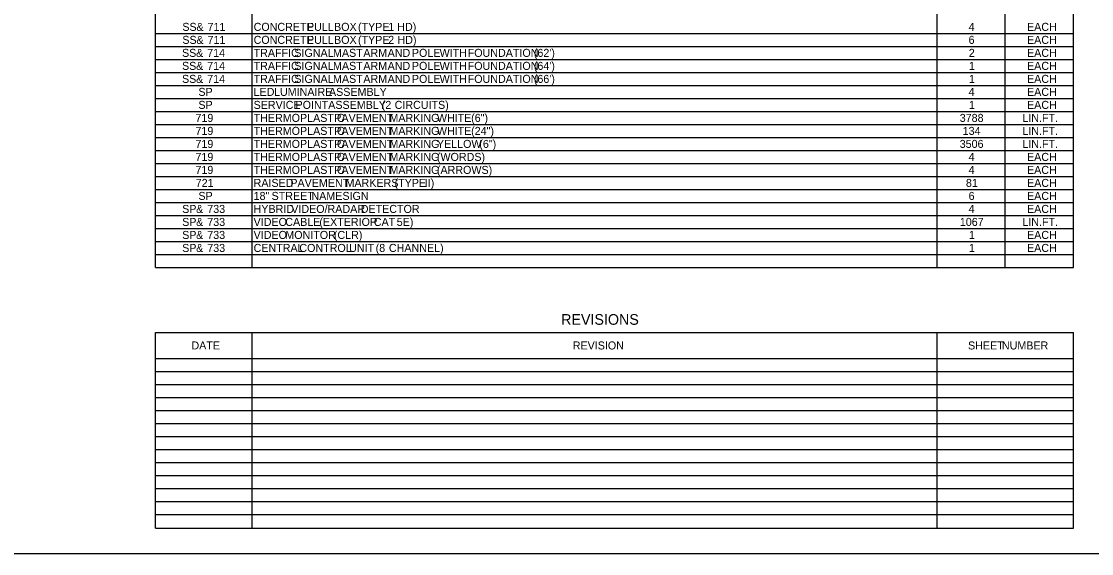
# Model space of a CAD drawing. Extents: x 3289 to 10164, y -1238 to -188.
# Drawn here: x 8800 to 9602, y -1238 to -839 of the extents above; entities that cross this region are included whole.
import ezdxf

# ---------------------------------------------------------------- set-up
doc = ezdxf.new("R2010")
doc.units = 0
for name, color, linetype in [('Default', 7, 'Continuous'), ('DSN_DRFT_Named-Boundary', 7, 'Continuous'), ('DSN_QNTY_Annotation', 7, 'Continuous')]:
    doc.layers.add(name, color=color, linetype=linetype)

msp = doc.modelspace()

# ---------------------------------------------------------------- linework, layer by layer
at = {"layer": 'DSN_DRFT_Named-Boundary'}
msp.add_lwpolyline([(8538.57, -1237.74), (10163.57, -1237.74), (10163.57, -187.74), (8538.57, -187.74)], close=True, dxfattribs=at)
at = {"layer": 'DSN_QNTY_Annotation'}
for p, q in [((8900.84, -1023.18), (8900.84, -223.68)), ((8973.38, -1023.18), (8973.38, -223.68)), ((9486.62, -1023.18), (9486.62, -223.68)), ((9537.71, -1023.18), (9537.71, -223.68)), ((9537.71, -1023.18), (9537.71, -223.68)), ((9588.8, -1023.18), (9588.8, -223.68)), ((8973.38, -1023.18), (8973.38, -252.93)), ((8900.84, -847.68), (9588.8, -847.68)), ((9486.62, -1023.18), (9486.62, -847.68)), ((8900.84, -857.43), (9588.8, -857.43)), ((9396.53, -857.43), (9486.62, -857.43)), ((9486.62, -857.43), (9588.8, -857.43)), ((8900.84, -867.18), (9588.8, -867.18)), ((8900.84, -876.93), (9588.8, -876.93)), ((8900.84, -886.68), (9588.8, -886.68)), ((8900.84, -896.43), (9588.8, -896.43)), ((8900.84, -906.18), (9588.8, -906.18)), ((8900.84, -915.93), (9588.8, -915.93)), ((8900.84, -925.68), (9588.8, -925.68)), ((8900.84, -935.43), (9588.8, -935.43)), ((8900.84, -945.18), (9588.8, -945.18)), ((8900.84, -954.93), (9588.8, -954.93)), ((8900.84, -964.68), (9588.8, -964.68)), ((8900.84, -974.43), (9588.8, -974.43)), ((8900.84, -984.18), (9588.8, -984.18)), ((8900.84, -993.93), (9588.8, -993.93)), ((8900.84, -1003.68), (9588.8, -1003.68)), ((8900.84, -1013.43), (9588.8, -1013.43)), ((8900.84, -1023.18), (9588.8, -1023.18)), ((8900.84, -1071.93), (9588.8, -1071.93)), ((8900.84, -1071.93), (8973.38, -1071.93)), ((8900.84, -1218.57), (8900.84, -1071.93)), ((8973.38, -1218.57), (8973.38, -1071.93)), ((9486.62, -1071.93), (9588.8, -1071.93)), ((9486.62, -1091.43), (9486.62, -1071.93)), ((9486.62, -1218.57), (9486.62, -1071.93)), ((9588.8, -1218.57), (9588.8, -1071.93)), ((8900.84, -1091.43), (9588.8, -1091.43)), ((8900.84, -1101.18), (9588.8, -1101.18)), ((8900.84, -1110.93), (9588.8, -1110.93)), ((8900.84, -1120.68), (9588.8, -1120.68)), ((8900.84, -1130.43), (9588.8, -1130.43)), ((8900.84, -1140.18), (9588.8, -1140.18)), ((8900.84, -1149.93), (9588.8, -1149.93)), ((8900.84, -1159.68), (9588.8, -1159.68)), ((8900.84, -1169.43), (9588.8, -1169.43)), ((8900.84, -1179.18), (9588.8, -1179.18)), ((8900.84, -1188.93), (9588.8, -1188.93)), ((8900.84, -1198.68), (9588.8, -1198.68)), ((8900.84, -1208.43), (9588.8, -1208.43)), ((8900.84, -1218.57), (9588.8, -1218.57))]:
    msp.add_line(p, q, dxfattribs=at)

# ---------------------------------------------------------------- texts
at = {"layer": 'Default'}
for s, height, p in [('SS', 6, (8920.95, -845.81)), (' &', 6, (8929.26, -845.81)), (' 711', 6, (8937.6, -845.81)), ('CONCRETE', 6, (8974.36, -845.81)), (' PULL', 6, (9012.13, -845.81)), (' BOX', 6, (9032.42, -845.81)), (' (TYPE', 6, (9050.36, -845.81)), (' 1', 6, (9073.01, -845.81)), (' HD)', 6, (9079.8, -845.81)), ('4', 6, (9510.23, -845.81)), ('EACH', 6, (9554.03, -845.81)), ('SS', 6, (8920.95, -855.56)), (' &', 6, (8929.26, -855.56)), (' 711', 6, (8937.6, -855.56)), ('CONCRETE', 6, (8974.36, -855.56)), (' PULL', 6, (9012.13, -855.56)), (' BOX', 6, (9032.42, -855.56)), (' (TYPE', 6, (9050.36, -855.56)), (' 2', 6, (9073.01, -855.56)), (' HD)', 6, (9079.98, -855.56)), ('6', 6, (9510.25, -855.56)), ('EACH', 6, (9554.03, -855.56)), ('SS', 6, (8920.71, -865.31)), (' &', 6, (8929.01, -865.31)), (' 714', 6, (8937.36, -865.31)), ('TRAFFIC', 6, (8974.36, -865.31)), (' SIGNAL', 6, (9002.66, -865.31)), (' MAST', 6, (9031.64, -865.31)), (' ARM', 6, (9054.38, -865.31)), (' AND', 6, (9072.58, -865.31)), (' POLE', 6, (9090.77, -865.31)), (' WITH', 6, (9111.56, -865.31)), (' FOUNDATION', 6, (9132.58, -865.31)), (" (62')", 6, (9182.15, -865.31)), ('2', 6, (9510.38, -865.31)), ('EACH', 6, (9554.03, -865.31)), ('SS', 6, (8920.71, -875.06)), (' &', 6, (8929.01, -875.06)), (' 714', 6, (8937.36, -875.06)), ('TRAFFIC', 6, (8974.36, -875.06)), (' SIGNAL', 6, (9002.66, -875.06)), (' MAST', 6, (9031.64, -875.06)), (' ARM', 6, (9054.38, -875.06)), (' AND', 6, (9072.58, -875.06)), (' POLE', 6, (9090.77, -875.06)), (' WITH', 6, (9111.56, -875.06)), (' FOUNDATION', 6, (9132.58, -875.06)), (" (64')", 6, (9182.15, -875.06)), ('1', 6, (9510.47, -875.06)), ('EACH', 6, (9554.03, -875.06)), ('SS', 6, (8920.71, -884.81)), (' &', 6, (8929.01, -884.81)), (' 714', 6, (8937.36, -884.81)), ('TRAFFIC', 6, (8974.36, -884.81)), (' SIGNAL', 6, (9002.66, -884.81)), (' MAST', 6, (9031.64, -884.81)), (' ARM', 6, (9054.38, -884.81)), (' AND', 6, (9072.58, -884.81)), (' POLE', 6, (9090.77, -884.81)), (' WITH', 6, (9111.56, -884.81)), (' FOUNDATION', 6, (9132.58, -884.81)), (" (66')", 6, (9182.15, -884.81)), ('1', 6, (9510.47, -884.81)), ('EACH', 6, (9554.03, -884.81)), ('SP', 6, (8932.99, -894.56)), ('LED', 6, (8974.36, -894.56)), (' LUMINAIRE', 6, (8987.45, -894.56)), (' ASSEMBLY', 6, (9028.63, -894.56)), ('4', 6, (9510.23, -894.56)), ('EACH', 6, (9554.03, -894.56)), ('SP', 6, (8932.99, -904.31)), ('SERVICE', 6, (8974.36, -904.31)), (' POINT', 6, (9003.55, -904.31)), (' ASSEMBLY', 6, (9028.05, -904.31)), (' (2', 6, (9068.16, -904.31)), (' CIRCUITS)', 6, (9077.85, -904.31)), ('1', 6, (9510.47, -904.31)), ('EACH', 6, (9554.03, -904.31)), ('719', 6, (8930.78, -914.06)), ('THERMOPLASTIC', 6, (8974.36, -914.06)), (' PAVEMENT', 6, (9032.6, -914.06)), (' MARKING', 6, (9073.94, -914.06)), (' WHITE', 6, (9109.51, -914.06)), (' (6")', 6, (9135.17, -914.06)), ('3788', 6, (9503.61, -914.06)), ('LIN.', 6, (9550.54, -914.06)), (' FT.', 6, (9563, -914.06)), ('719', 6, (8930.78, -923.81)), ('THERMOPLASTIC', 6, (8974.36, -923.81)), (' PAVEMENT', 6, (9032.6, -923.81)), (' MARKING', 6, (9073.94, -923.81)), (' WHITE', 6, (9109.51, -923.81)), (' (24")', 6, (9135.17, -923.81)), ('134', 6, (9505.79, -923.81)), ('LIN.', 6, (9550.54, -923.81)), (' FT.', 6, (9563, -923.81)), ('719', 6, (8930.78, -933.56)), ('THERMOPLASTIC', 6, (8974.36, -933.56)), (' PAVEMENT', 6, (9032.6, -933.56)), (' MARKING', 6, (9073.94, -933.56)), (' YELLOW', 6, (9109.51, -933.56)), (' (6")', 6, (9141.31, -933.56)), ('3506', 6, (9503.59, -933.56)), ('LIN.', 6, (9550.54, -933.56)), (' FT.', 6, (9563, -933.56)), ('719', 6, (8930.78, -943.31)), ('THERMOPLASTIC', 6, (8974.36, -943.31)), (' PAVEMENT', 6, (9032.6, -943.31)), (' MARKING', 6, (9073.94, -943.31)), (' (WORDS)', 6, (9109.51, -943.31)), ('4', 6, (9510.23, -943.31)), ('EACH', 6, (9554.03, -943.31)), ('719', 6, (8930.78, -953.06)), ('THERMOPLASTIC', 6, (8974.36, -953.06)), (' PAVEMENT', 6, (9032.6, -953.06)), (' MARKING', 6, (9073.94, -953.06)), (' (ARROWS)', 6, (9109.51, -953.06)), ('4', 6, (9510.23, -953.06)), ('EACH', 6, (9554.03, -953.06)), ('721', 6, (8930.97, -962.81)), ('RAISED', 6, (8974.36, -962.81)), (' PAVEMENT', 6, (8999.67, -962.81)), (' MARKERS', 6, (9041.01, -962.81)), (' (TYPE', 6, (9077.77, -962.81)), (' II)', 6, (9100.42, -962.81)), ('81', 6, (9508.25, -962.81)), ('EACH', 6, (9554.03, -962.81)), ('SP', 6, (8932.99, -972.56)), ('18"', 6, (8974.36, -972.56)), (' STREET', 6, (8985.61, -972.56)), (' NAME', 6, (9015.48, -972.56)), (' SIGN', 6, (9038.7, -972.56)), ('6', 6, (9510.25, -972.56)), ('EACH', 6, (9554.03, -972.56)), ('SP', 6, (8920.83, -982.31)), (' &', 6, (8929.06, -982.31)), (' 733', 6, (8937.4, -982.31)), ('HYBRID', 6, (8974.36, -982.31)), (' VIDEO/RADAR', 6, (9000.36, -982.31)), (' DETECTOR', 6, (9052.42, -982.31)), ('4', 6, (9510.23, -982.31)), ('EACH', 6, (9554.03, -982.31)), ('SP', 6, (8920.83, -992.06)), (' &', 6, (8929.06, -992.06)), (' 733', 6, (8937.4, -992.06)), ('VIDEO', 6, (8974.36, -992.06)), (' CABLE', 6, (8995.9, -992.06)), (' (EXTERIOR', 6, (9021.42, -992.06)), (' CAT', 6, (9062.24, -992.06)), (' 5E)', 6, (9079.4, -992.06)), ('1067', 6, (9503.67, -992.06)), ('LIN.', 6, (9550.54, -992.06)), (' FT.', 6, (9563, -992.06)), ('SP', 6, (8920.83, -1001.81)), (' &', 6, (8929.06, -1001.81)), (' 733', 6, (8937.4, -1001.81)), ('VIDEO', 6, (8974.36, -1001.81)), (' MONITOR', 6, (8995.9, -1001.81)), (' (CLR)', 6, (9032.29, -1001.81)), ('1', 6, (9510.47, -1001.81)), ('EACH', 6, (9554.03, -1001.81)), ('SP', 6, (8920.83, -1011.56)), (' &', 6, (8929.06, -1011.56)), (' 733', 6, (8937.4, -1011.56)), ('CENTRAL', 6, (8974.36, -1011.56)), (' CONTROL', 6, (9006.43, -1011.56)), (' UNIT', 6, (9043.71, -1011.56)), (' (8', 6, (9063.61, -1011.56)), (' CHANNEL)', 6, (9073.53, -1011.56)), ('1', 6, (9510.47, -1011.56)), ('EACH', 6, (9554.03, -1011.56)), ('REVISIONS', 8, (9204.84, -1066.18)), ('DATE', 6, (8927.77, -1084.68)), ('REVISION', 6, (9213.57, -1084.68)), ('SHEET', 6, (9509.83, -1084.68)), (' NUMBER', 6, (9533, -1084.68))]:
    msp.add_text(s, height=height, dxfattribs=at).set_placement(p)

doc.saveas('drawing.dxf')
